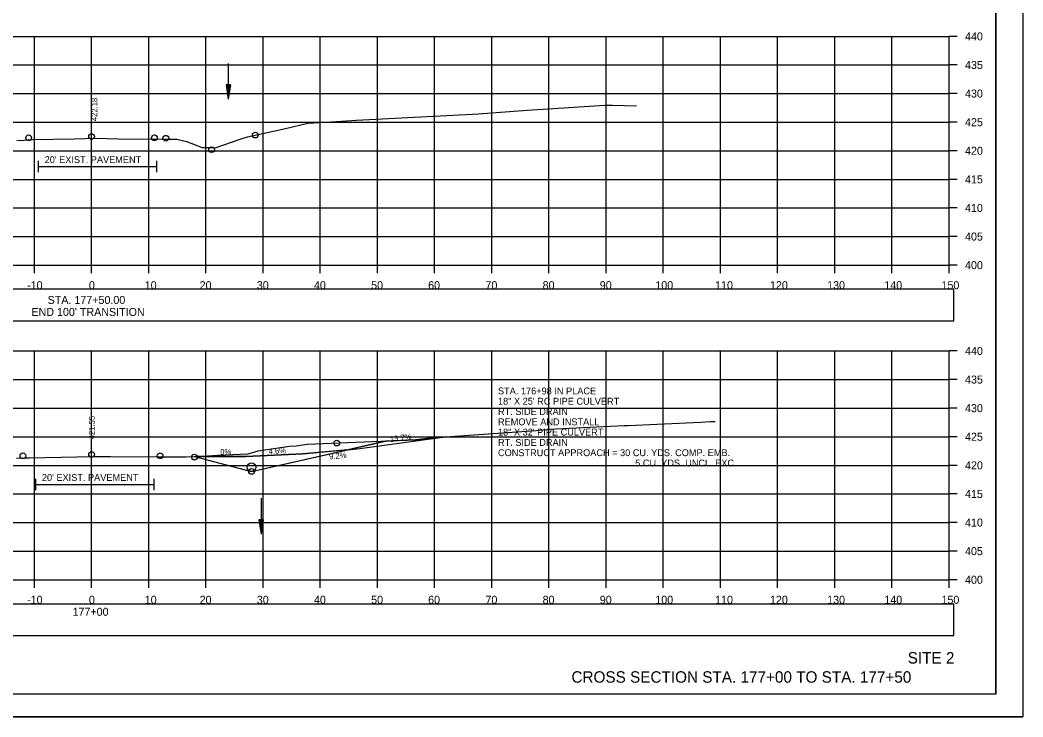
# Model space of a CAD drawing. Extents: x 1376273 to 1384221, y 378927 to 384592.
# Drawn here: x 1378212 to 1378387.4, y 382245.2 to 382367.1 of the extents above; entities that cross this region are included whole.
import ezdxf

# ---------------------------------------------------------------- set-up
doc = ezdxf.new("R2010")
doc.units = 0
for name, color, linetype in [('R_Alt Surface', 7, 'Continuous'), ('R_Axis', 7, 'Continuous'), ('R_Axis Annot', 7, 'Continuous'), ('R_Border', 7, 'Continuous'), ('R_Draft', 7, 'Continuous'), ('R_Drive', 7, 'Continuous'), ('R_Exist Surface', 7, 'Continuous'), ('R_Grid', 7, 'Continuous'), ('R_No Plot', 7, 'Continuous'), ('R_Water', 7, 'Continuous'), ('R_Xsect Elev', 7, 'Continuous'), ('T_Notes', 7, 'Continuous')]:
    doc.layers.add(name, color=color, linetype=linetype)

msp = doc.modelspace()

# ---------------------------------------------------------------- linework, layer by layer
at = {"layer": 'R_Alt Surface'}
for points in [[(1378215.11, 382342.44), (1378215.11, 382340.44)], [(1378215.11, 382341.44), (1378235.81, 382341.44)], [(1378235.81, 382342.44), (1378235.81, 382340.44)], [(1378214.63, 382286.87), (1378214.63, 382284.87)], [(1378235.33, 382286.87), (1378235.33, 382284.87)], [(1378214.63, 382285.87), (1378235.33, 382285.87)]]:
    msp.add_lwpolyline(points, dxfattribs=at)
at = {"layer": 'R_Axis'}
for p, q in [((1378374.46, 382324.2), (1378374.46, 382364.2)), ((1378375.86, 382364.2), (1378374.46, 382364.2)), ((1378375.86, 382359.2), (1378374.46, 382359.2)), ((1378375.86, 382354.2), (1378374.46, 382354.2)), ((1378375.86, 382349.2), (1378374.46, 382349.2)), ((1378375.86, 382344.2), (1378374.46, 382344.2)), ((1378375.86, 382339.2), (1378374.46, 382339.2)), ((1378375.86, 382334.2), (1378374.46, 382334.2)), ((1378375.86, 382329.2), (1378374.46, 382329.2)), ((1378074.46, 382324.2), (1378374.46, 382324.2)), ((1378214.46, 382322.8), (1378214.46, 382324.2)), ((1378224.46, 382322.8), (1378224.46, 382324.2)), ((1378234.46, 382322.8), (1378234.46, 382324.2)), ((1378244.46, 382322.8), (1378244.46, 382324.2)), ((1378254.46, 382322.8), (1378254.46, 382324.2)), ((1378264.46, 382322.8), (1378264.46, 382324.2)), ((1378274.46, 382322.8), (1378274.46, 382324.2)), ((1378284.46, 382322.8), (1378284.46, 382324.2)), ((1378294.46, 382322.8), (1378294.46, 382324.2)), ((1378304.46, 382322.8), (1378304.46, 382324.2)), ((1378314.46, 382322.8), (1378314.46, 382324.2)), ((1378324.46, 382322.8), (1378324.46, 382324.2)), ((1378334.46, 382322.8), (1378334.46, 382324.2)), ((1378344.46, 382322.8), (1378344.46, 382324.2)), ((1378354.46, 382322.8), (1378354.46, 382324.2)), ((1378364.46, 382322.8), (1378364.46, 382324.2)), ((1378374.46, 382322.8), (1378374.46, 382324.2)), ((1378375.86, 382324.2), (1378374.46, 382324.2)), ((1378374.46, 382269.2), (1378374.46, 382309.2)), ((1378375.86, 382309.2), (1378374.46, 382309.2)), ((1378375.86, 382304.2), (1378374.46, 382304.2)), ((1378375.86, 382299.2), (1378374.46, 382299.2)), ((1378375.86, 382294.2), (1378374.46, 382294.2)), ((1378375.86, 382289.2), (1378374.46, 382289.2)), ((1378375.86, 382284.2), (1378374.46, 382284.2)), ((1378375.86, 382279.2), (1378374.46, 382279.2)), ((1378375.86, 382274.2), (1378374.46, 382274.2)), ((1378074.46, 382269.2), (1378374.46, 382269.2)), ((1378214.46, 382267.8), (1378214.46, 382269.2)), ((1378224.46, 382267.8), (1378224.46, 382269.2)), ((1378234.46, 382267.8), (1378234.46, 382269.2)), ((1378244.46, 382267.8), (1378244.46, 382269.2)), ((1378254.46, 382267.8), (1378254.46, 382269.2)), ((1378264.46, 382267.8), (1378264.46, 382269.2)), ((1378274.46, 382267.8), (1378274.46, 382269.2)), ((1378284.46, 382267.8), (1378284.46, 382269.2)), ((1378294.46, 382267.8), (1378294.46, 382269.2)), ((1378304.46, 382267.8), (1378304.46, 382269.2)), ((1378314.46, 382267.8), (1378314.46, 382269.2)), ((1378324.46, 382267.8), (1378324.46, 382269.2)), ((1378334.46, 382267.8), (1378334.46, 382269.2)), ((1378344.46, 382267.8), (1378344.46, 382269.2)), ((1378354.46, 382267.8), (1378354.46, 382269.2)), ((1378364.46, 382267.8), (1378364.46, 382269.2)), ((1378374.46, 382267.8), (1378374.46, 382269.2)), ((1378375.86, 382269.2), (1378374.46, 382269.2))]:
    msp.add_line(p, q, dxfattribs=at)
at = {"layer": 'R_Axis Annot'}
for points in [[(1378073.48, 382314.48), (1378375.28, 382314.48), (1378375.28, 382320), (1378073.48, 382320)], [(1378073.48, 382259.43), (1378375.28, 382259.43), (1378375.28, 382264.95), (1378073.48, 382264.95)]]:
    msp.add_lwpolyline(points, close=True, dxfattribs=at)
at = {"layer": 'R_Border'}
for q in [(1378382.64, 382454.66), (1378066.46, 382249.2)]:
    msp.add_line((1378382.64, 382249.2), q, dxfattribs=at)
at = {"layer": 'R_Drive'}
for p, q in [((1378271.4, 382292.14), (1378286.33, 382294.18)), ((1378261.45, 382291.22), (1378271.4, 382292.14)), ((1378242.46, 382290.76), (1378251.46, 382290.76)), ((1378251.46, 382290.76), (1378261.45, 382291.22))]:
    msp.add_line(p, q, dxfattribs=at)
at = {"layer": 'R_Exist Surface'}
for points in [[(1378211.38, 382346.01), (1378212.61, 382346.06), (1378214.11, 382346.16), (1378221.43, 382346.31), (1378225.16, 382346.38), (1378229.1, 382346.31), (1378236.81, 382346.25), (1378237.69, 382346.25), (1378239.4, 382346.22), (1378241.12, 382345.83), (1378241.19, 382345.8), (1378241.27, 382345.78), (1378243.82, 382344.79), (1378245.22, 382344.75), (1378246.1, 382344.72), (1378250.46, 382346.21), (1378251.77, 382346.66), (1378258.4, 382348.07), (1378262.27, 382349.01), (1378266.42, 382349.25), (1378270.8, 382349.57), (1378282.04, 382350.13), (1378292.15, 382350.65), (1378300.64, 382351.3), (1378314.25, 382352.19), (1378315.57, 382352.19), (1378319.78, 382352.07)], [(1378211.31, 382290.45), (1378212.93, 382290.51), (1378213.63, 382290.52), (1378221.91, 382290.68), (1378224.7, 382290.75), (1378227.78, 382290.75), (1378236.33, 382290.71), (1378237.55, 382290.69), (1378239.06, 382290.67), (1378239.12, 382290.67), (1378240.93, 382290.7), (1378243.87, 382290.81), (1378246.51, 382290.99), (1378251.86, 382291.24), (1378253.59, 382291.74), (1378259.1, 382292.58), (1378260.28, 382292.61), (1378262.19, 382292.91), (1378273.57, 382293.35), (1378281.17, 382293.64), (1378284.7, 382294.07), (1378302.24, 382295.32), (1378303.48, 382295.42), (1378305.69, 382295.57), (1378317.61, 382296.16), (1378318.33, 382296.16), (1378331.07, 382296.77), (1378332.75, 382296.86), (1378333.19, 382296.86), (1378333.41, 382296.86), (1378333.56, 382296.85)]]:
    msp.add_lwpolyline(points, dxfattribs=at)
at = {"layer": 'R_Grid'}
for p, q in [((1378074.46, 382364.2), (1378374.46, 382364.2)), ((1378214.46, 382324.2), (1378214.46, 382364.2)), ((1378224.46, 382324.2), (1378224.46, 382364.2)), ((1378234.46, 382324.2), (1378234.46, 382364.2)), ((1378244.46, 382324.2), (1378244.46, 382364.2)), ((1378254.46, 382324.2), (1378254.46, 382364.2)), ((1378264.46, 382324.2), (1378264.46, 382364.2)), ((1378274.46, 382324.2), (1378274.46, 382364.2)), ((1378284.46, 382324.2), (1378284.46, 382364.2)), ((1378294.46, 382324.2), (1378294.46, 382364.2)), ((1378304.46, 382324.2), (1378304.46, 382364.2)), ((1378314.46, 382324.2), (1378314.46, 382364.2)), ((1378324.46, 382324.2), (1378324.46, 382364.2)), ((1378334.46, 382324.2), (1378334.46, 382364.2)), ((1378344.46, 382324.2), (1378344.46, 382364.2)), ((1378354.46, 382324.2), (1378354.46, 382364.2)), ((1378364.46, 382324.2), (1378364.46, 382364.2)), ((1378374.46, 382324.2), (1378374.46, 382364.2)), ((1378074.46, 382359.2), (1378374.46, 382359.2)), ((1378074.46, 382354.2), (1378374.46, 382354.2)), ((1378074.46, 382349.2), (1378374.46, 382349.2)), ((1378074.46, 382344.2), (1378374.46, 382344.2)), ((1378074.46, 382339.2), (1378374.46, 382339.2)), ((1378074.46, 382334.2), (1378374.46, 382334.2)), ((1378074.46, 382329.2), (1378374.46, 382329.2)), ((1378074.46, 382324.2), (1378374.46, 382324.2)), ((1378074.46, 382309.2), (1378374.46, 382309.2)), ((1378214.46, 382269.2), (1378214.46, 382309.2)), ((1378224.46, 382269.2), (1378224.46, 382309.2)), ((1378234.46, 382269.2), (1378234.46, 382309.2)), ((1378244.46, 382269.2), (1378244.46, 382309.2)), ((1378254.46, 382269.2), (1378254.46, 382309.2)), ((1378264.46, 382269.2), (1378264.46, 382309.2)), ((1378274.46, 382269.2), (1378274.46, 382309.2)), ((1378284.46, 382269.2), (1378284.46, 382309.2)), ((1378294.46, 382269.2), (1378294.46, 382309.2)), ((1378304.46, 382269.2), (1378304.46, 382309.2)), ((1378314.46, 382269.2), (1378314.46, 382309.2)), ((1378324.46, 382269.2), (1378324.46, 382309.2)), ((1378334.46, 382269.2), (1378334.46, 382309.2)), ((1378344.46, 382269.2), (1378344.46, 382309.2)), ((1378354.46, 382269.2), (1378354.46, 382309.2)), ((1378364.46, 382269.2), (1378364.46, 382309.2)), ((1378374.46, 382269.2), (1378374.46, 382309.2)), ((1378074.46, 382304.2), (1378374.46, 382304.2)), ((1378074.46, 382299.2), (1378374.46, 382299.2)), ((1378074.46, 382294.2), (1378374.46, 382294.2)), ((1378074.46, 382289.2), (1378374.46, 382289.2)), ((1378074.46, 382284.2), (1378374.46, 382284.2)), ((1378074.46, 382279.2), (1378374.46, 382279.2)), ((1378074.46, 382274.2), (1378374.46, 382274.2)), ((1378074.46, 382269.2), (1378374.46, 382269.2))]:
    msp.add_line(p, q, dxfattribs=at)
at = {"layer": 'R_No Plot'}
msp.add_line((1378054.06, 382245.22), (1378387.39, 382245.22), dxfattribs=at)
for points in [[(1378054.05, 382458.55), (1378387.39, 382458.55), (1378387.39, 382245.22), (1378054.05, 382245.22)], [(1378300.38, 382454.66), (1378300.38, 382444.78), (1378336.11, 382444.78), (1378336.11, 382441.86), (1378359.31, 382441.86), (1378359.31, 382417.53), (1378382.64, 382417.53), (1378382.64, 382249.2), (1378066.46, 382249.2), (1378066.46, 382454.66)]]:
    msp.add_lwpolyline(points, close=True, dxfattribs=at)
msp.add_lwpolyline([(1378242.46, 382290.76), (1378252.46, 382288.14), (1378275.89, 382293.43)], dxfattribs=at)
for centre in [(1378213.46, 382346.47), (1378224.46, 382346.69), (1378235.46, 382346.47), (1378237.46, 382346.39), (1378253.1, 382346.94), (1378245.46, 382344.39), (1378267.35, 382293.1), (1378212.46, 382290.88), (1378224.46, 382291.12), (1378236.46, 382290.88), (1378242.46, 382290.64), (1378252.46, 382288.14)]:
    msp.add_circle(centre, 0.5, dxfattribs=at)
at = {"layer": 'R_Water'}
for p, q in [((1378248.37, 382359.47), (1378248.37, 382353.22)), ((1378248, 382355.72), (1378248.37, 382353.22)), ((1378248.75, 382355.72), (1378248, 382355.72)), ((1378248.06, 382355.72), (1378248.37, 382353.63)), ((1378248.12, 382355.72), (1378248.37, 382354.06)), ((1378248.19, 382355.72), (1378248.37, 382354.48)), ((1378248.25, 382355.72), (1378248.37, 382354.9)), ((1378248.31, 382355.72), (1378248.37, 382355.32)), ((1378248.75, 382355.72), (1378248.37, 382353.22)), ((1378248.49, 382355.72), (1378248.37, 382354.9)), ((1378248.62, 382355.72), (1378248.37, 382354.06)), ((1378248.68, 382355.72), (1378248.37, 382353.63)), ((1378248.56, 382355.72), (1378248.37, 382354.48)), ((1378248.43, 382355.72), (1378248.37, 382355.32)), ((1378254.13, 382283.44), (1378254.13, 382277.19)), ((1378253.75, 382279.69), (1378254.13, 382277.19)), ((1378254.5, 382279.69), (1378253.75, 382279.69)), ((1378253.82, 382279.69), (1378254.13, 382277.61)), ((1378253.88, 382279.69), (1378254.13, 382278.04)), ((1378253.94, 382279.69), (1378254.13, 382278.46)), ((1378254.01, 382279.69), (1378254.13, 382278.88)), ((1378254.07, 382279.69), (1378254.13, 382279.3)), ((1378254.5, 382279.69), (1378254.13, 382277.19)), ((1378254.25, 382279.69), (1378254.13, 382278.88)), ((1378254.38, 382279.69), (1378254.13, 382278.04)), ((1378254.44, 382279.69), (1378254.13, 382277.61)), ((1378254.31, 382279.69), (1378254.13, 382278.46)), ((1378254.19, 382279.69), (1378254.13, 382279.3))]:
    msp.add_line(p, q, dxfattribs=at)
msp.add_circle((1378252.46, 382288.89), 0.75, dxfattribs=at)
at = {"layer": 'T_Notes'}
for p, q in [((1378271.4, 382292.14), (1378286.33, 382294.18)), ((1378286.33, 382294.18), (1378284.7, 382294.07)), ((1378275.89, 382293.43), (1378269.27, 382291.94)), ((1378269.27, 382291.94), (1378271.4, 382292.14)), ((1378251.46, 382290.76), (1378242.94, 382290.76)), ((1378242.96, 382290.63), (1378251.97, 382288.27)), ((1378261.45, 382291.22), (1378251.46, 382290.76)), ((1378252.94, 382288.25), (1378269.27, 382291.94)), ((1378269.27, 382291.94), (1378261.45, 382291.22))]:
    msp.add_line(p, q, dxfattribs=at)
for points in [[(1378284.7, 382294.07), (1378281.17, 382293.64), (1378275.89, 382293.43)], [(1378252.09, 382288.24), (1378252.46, 382288.14), (1378252.78, 382288.21)]]:
    msp.add_lwpolyline(points, dxfattribs=at)
for centre, radius, start, end in [((1378242.46, 382290.64), 0.5, 358.4227, 13.5374), ((1378252.46, 382288.14), 0.5, 160.5288, 165.3344), ((1378252.46, 382288.89), 0.75, 231.0576, 240.6687), ((1378252.46, 382288.89), 0.75, 295.4549, 308.9424), ((1378252.46, 382288.14), 0.5, 12.7275, 19.4712)]:
    msp.add_arc(centre, radius, start, end, dxfattribs=at)

# ---------------------------------------------------------------- texts
at = {"layer": 'R_Alt Surface'}
for p in [(1378216.26, 382342.05), (1378215.78, 382286.48)]:
    msp.add_text("20' EXIST. PAVEMENT", height=1.2, dxfattribs=at).set_placement(p)
at = {"layer": 'R_Axis Annot'}
for s, height, p in [('440', 1.4, (1378377.26, 382363.5)), ('435', 1.4, (1378377.26, 382358.5)), ('430', 1.4, (1378377.26, 382353.5)), ('425', 1.4, (1378377.26, 382348.5)), ('420', 1.4, (1378377.26, 382343.5)), ('415', 1.4, (1378377.26, 382338.5)), ('410', 1.4, (1378377.26, 382333.5)), ('405', 1.4, (1378377.26, 382328.5)), ('400', 1.4, (1378377.26, 382323.5)), ('-10', 1.4, (1378213.19, 382320)), ('0', 1.4, (1378224, 382320)), ('10', 1.4, (1378233.77, 382320)), ('20', 1.4, (1378243.37, 382320)), ('30', 1.4, (1378253.37, 382320)), ('40', 1.4, (1378263.37, 382320)), ('50', 1.4, (1378273.37, 382320)), ('60', 1.4, (1378283.34, 382320)), ('70', 1.4, (1378293.37, 382320)), ('80', 1.4, (1378303.37, 382320)), ('90', 1.4, (1378313.37, 382320)), ('100', 1.4, (1378323.08, 382320)), ('110', 1.4, (1378333.54, 382320)), ('120', 1.4, (1378343.14, 382320)), ('130', 1.4, (1378353.14, 382320)), ('140', 1.4, (1378363.14, 382320)), ('150', 1.4, (1378373.14, 382320)), ('STA. 177+50.00', 1.4, (1378216.78, 382317.42)), ("END 100' TRANSITION", 1.4, (1378213.95, 382315.32)), ('440', 1.4, (1378377.26, 382308.5)), ('435', 1.4, (1378377.26, 382303.5)), ('STA. 176+98 IN PLACE', 1.2, (1378295.56, 382301.61)), ('18" X 25\' RC PIPE CULVERT', 1.2, (1378295.56, 382299.81)), ('RT. SIDE DRAIN', 1.2, (1378295.56, 382298.01)), ('430', 1.4, (1378377.26, 382298.5)), ('REMOVE AND INSTALL', 1.2, (1378295.56, 382296.21)), ('18" X 32\' PIPE CULVERT', 1.2, (1378295.56, 382294.41)), ('RT. SIDE DRAIN', 1.2, (1378295.56, 382292.61)), ('425', 1.4, (1378377.26, 382293.5)), ('CONSTRUCT APPROACH = 30 CU. YDS. COMP. EMB.', 1.2, (1378295.56, 382290.81)), ('5 CU. YDS. UNCL. EXC.', 1.2, (1378319.56, 382289.01)), ('420', 1.4, (1378377.26, 382288.5)), ('415', 1.4, (1378377.26, 382283.5)), ('410', 1.4, (1378377.26, 382278.5)), ('405', 1.4, (1378377.26, 382273.5)), ('400', 1.4, (1378377.26, 382268.5)), ('-10', 1.4, (1378213.19, 382265)), ('0', 1.4, (1378224, 382265)), ('10', 1.4, (1378233.77, 382265)), ('20', 1.4, (1378243.37, 382265)), ('30', 1.4, (1378253.37, 382265)), ('40', 1.4, (1378263.37, 382265)), ('50', 1.4, (1378273.37, 382265)), ('60', 1.4, (1378283.34, 382265)), ('70', 1.4, (1378293.37, 382265)), ('80', 1.4, (1378303.37, 382265)), ('90', 1.4, (1378313.37, 382265)), ('100', 1.4, (1378323.08, 382265)), ('110', 1.4, (1378333.54, 382265)), ('120', 1.4, (1378343.14, 382265)), ('130', 1.4, (1378353.14, 382265)), ('140', 1.4, (1378363.14, 382265)), ('150', 1.4, (1378373.14, 382265)), ('177+00', 1.4, (1378221.14, 382262.9))]:
    msp.add_text(s, height=height, dxfattribs=at).set_placement(p)
at = {"layer": 'R_Draft'}
for s, p in [('SITE 2', (1378367.23, 382254.55)), ('CROSS SECTION STA. 177+00 TO STA. 177+50', (1378308.41, 382251.2))]:
    msp.add_text(s, height=2, dxfattribs=at).set_placement(p)
at = {"layer": 'R_Drive'}
for s, rotation, p in [('13.7%', 7.902, (1378276.72, 382293.26)), ('4.6%', 2.634, (1378255.46, 382291.18)), ('9.2%', 5.268, (1378266.07, 382290.23))]:
    msp.add_text(s, height=1, rotation=rotation, dxfattribs=at).set_placement(p)
msp.add_text('0%', height=1, dxfattribs=at).set_placement((1378246.97, 382291.06))
at = {"layer": 'R_Xsect Elev'}
for s, p in [('422.18', (1378225.46, 382349.38)), ('421.55', (1378225, 382293.75))]:
    msp.add_text(s, height=1, rotation=90, dxfattribs=at).set_placement(p)

doc.saveas('drawing.dxf')
